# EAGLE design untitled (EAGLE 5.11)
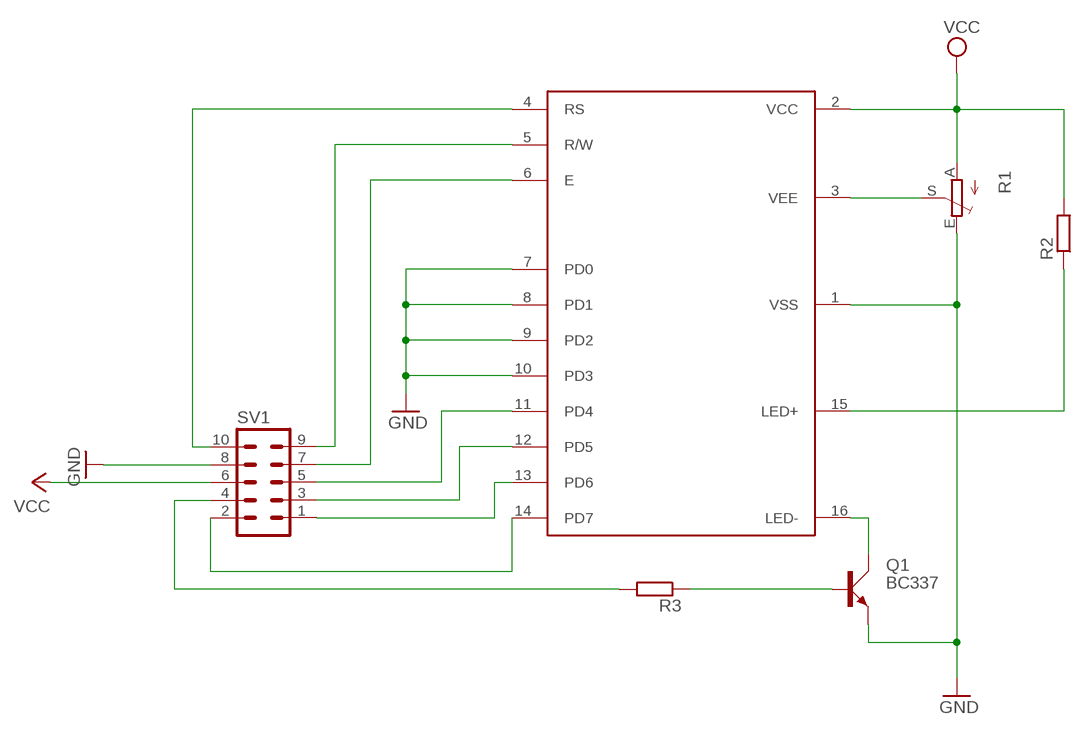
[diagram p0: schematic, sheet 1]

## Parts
Q1  BC337  [SOT54A]
R1  TRIM_EU-LI10  [LI10]
R2  R-EU_0207/10  [0207/10]
R3  R-EU_0207/10  [0207/10]
SV1  ML10L  [ML10L]
U$1  RTR  [TRTRR]

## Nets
GND: Q1.E R1.E SV1.8 U$1.1(VSS) U$1.7(PD0) U$1.8(PD1) U$1.9(PD2) U$1.10(PD3)
N$1: R1.S U$1.3(VEE)
N$3: Q1.C U$1.16(LED-)
N$4: Q1.B R3.1
N$5: R2.1 U$1.15(LED+)
N$6: SV1.2 U$1.14(PD7)
N$7: SV1.1 U$1.13(PD6)
N$8: SV1.3 U$1.12(PD5)
N$9: R3.2 SV1.4
N$10: SV1.7 U$1.6(E)
N$11: SV1.10 U$1.4(RS)
N$12: SV1.5 U$1.11(PD4)
N$14: SV1.9 U$1.5(R/W)
VCC: R1.A R2.2 SV1.6 U$1.2(VCC)

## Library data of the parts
Q1 = transistor-small-signal:BC337: NPN TRANSISTOR
R1 = pot:TRIM_EU-: POTENTIOMETER
R2 R3 = rcl:R-EU_: RESISTOR, European symbol
SV1 = con-ml:ML10L: HARTING; OC_FARNELL: unknown; OC_NEWARK: unknown
U$1 = 4x20lcd:RTR

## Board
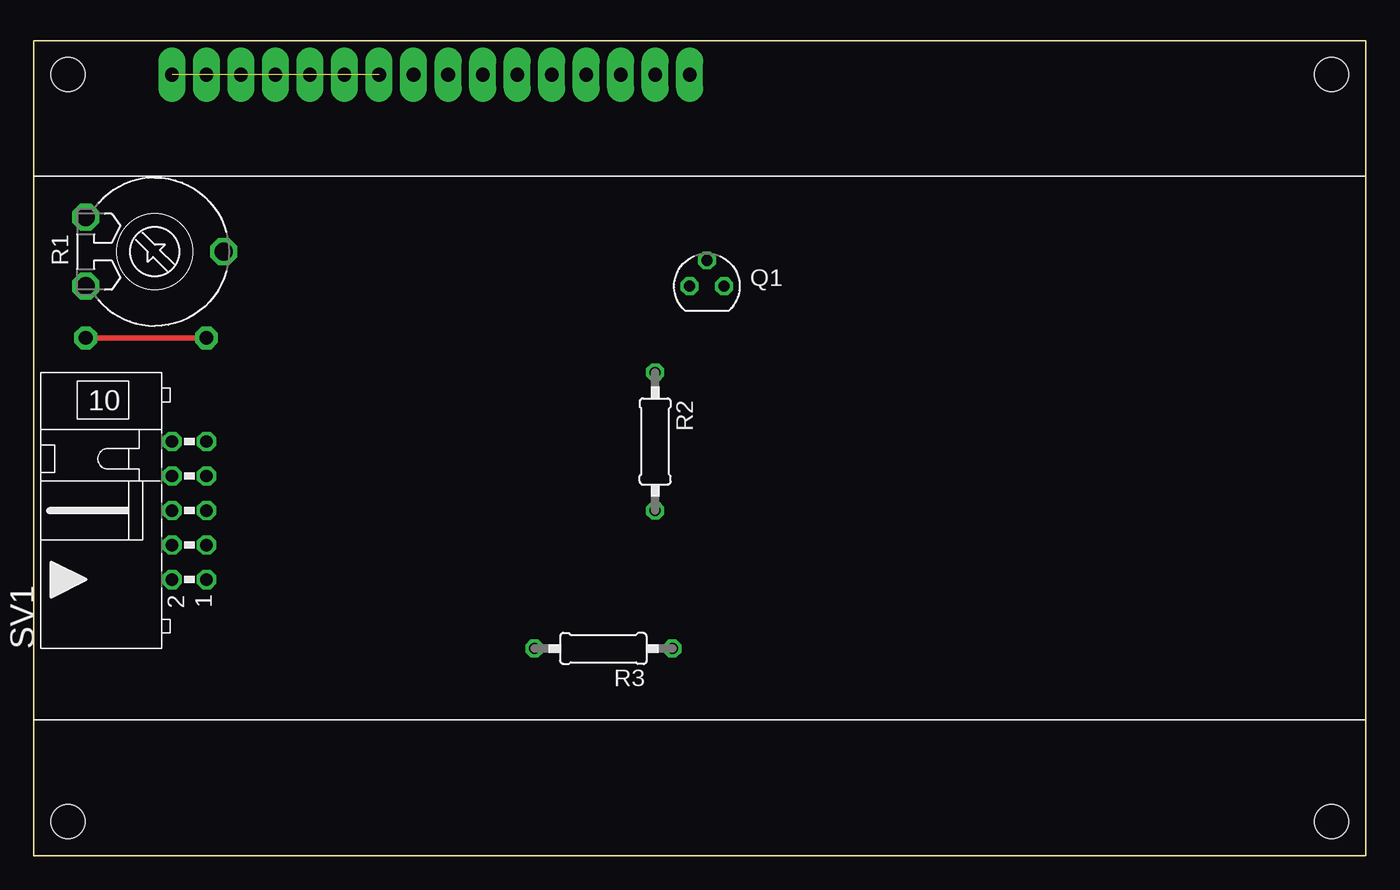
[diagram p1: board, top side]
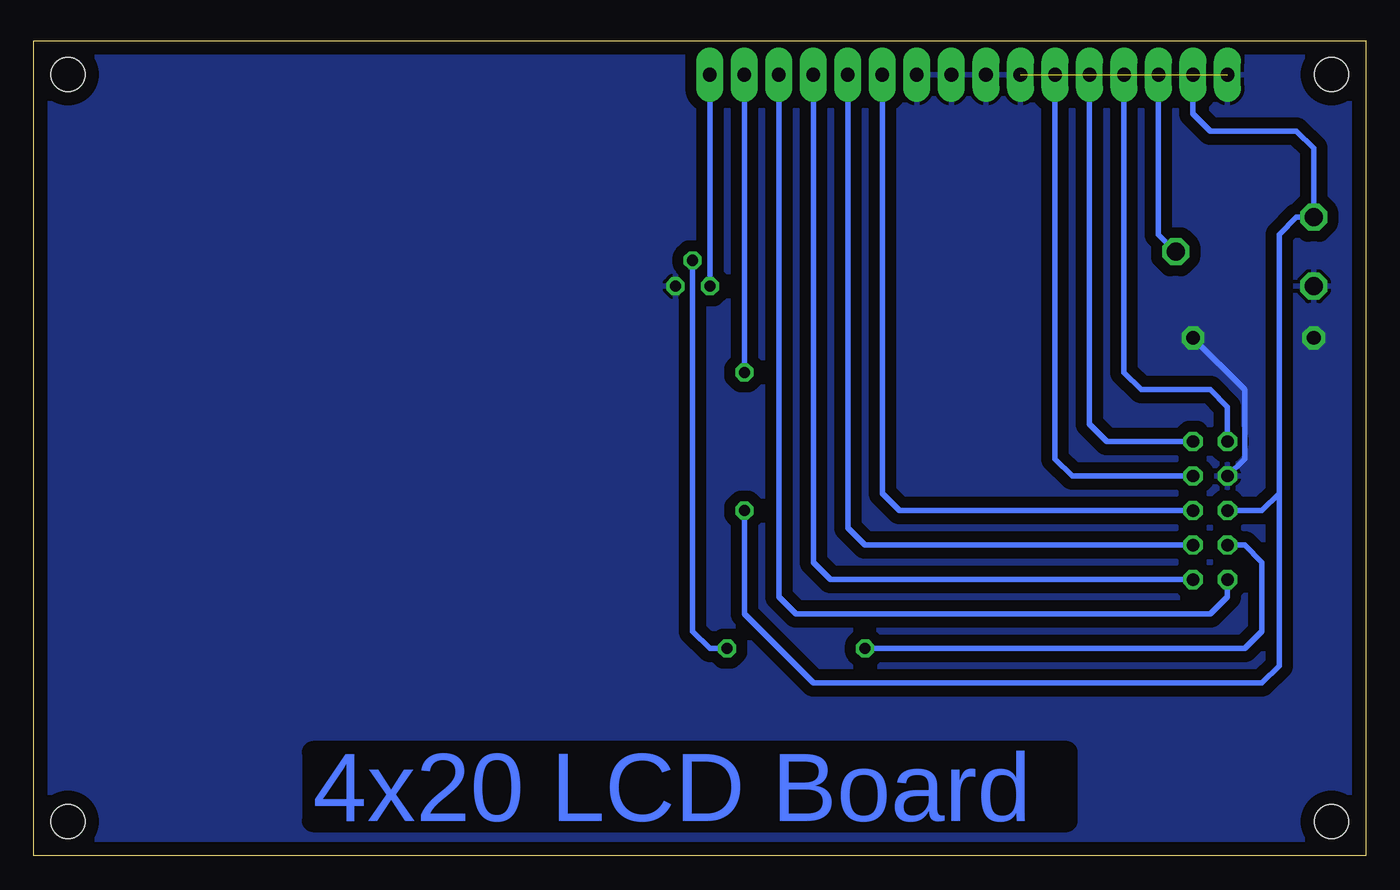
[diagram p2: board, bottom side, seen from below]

Size 98 x 60 mm. Coordinates in mm from the lower left corner, seen from the top.
Outline: 0,0 98,0 98,60 0,60 0,0
Copper layers (1*16): Top 0.035mm / dielectric 1.5mm / Bottom 0.035mm
Design rules "default": minimum track width 10mil, minimum drill 24mil, track to track 8mil, track to pad 8mil, pad to pad 8mil, via to via 8mil, smd to smd 8mil, copper to edge 40mil, drill to drill 8mil, minimum pad ring 10mil, minimum via ring 8mil, stop-mask expansion 4mil, vias tented up to drill 0mil, thermal gap 10mil

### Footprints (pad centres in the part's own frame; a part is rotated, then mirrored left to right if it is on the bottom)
SOT54A = drill 0.813 octagon: B 0,1.905; C -1.27,0; E 1.27,0
LI10 = drill 1.321 octagon: A -2.54,-5.08; E 2.54,-5.08; S 0,5.08
0207/10 = drill 0.813 octagon: 1 -5.08,0; 2 5.08,0
ML10L = drill 0.914 octagon: 1 -5.08,-1.27; 2 -5.08,1.27; 3 -2.54,-1.27; 4 -2.54,1.27; 5 0,-1.27; 6 0,1.27; 7 2.54,-1.27; 8 2.54,1.27; 9 5.08,-1.27; 10 5.08,1.27
TRTRR = drill 1 pad 2 long: 1 10.16,57.48; 2 12.7,57.48; 3 15.24,57.48; 4 17.78,57.48; 5 20.32,57.48; 6 22.86,57.48; 7 25.4,57.48; 8 27.94,57.48; 9 30.48,57.48; 10 33.02,57.48; 11 35.56,57.48; 12 38.1,57.48; 13 40.64,57.48; 14 43.18,57.48; 15 45.72,57.48; 16 48.26,57.48 | hole 2.5: 2.5,57.5; 95.5,57.5; 95.5,2.5; 2.5,2.5

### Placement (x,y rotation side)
DRILEGEND  [DRILEGEND]  not placed on the board
Q1  49.53,41.91 0 top
R1  8.89,44.45 270 top
R2  45.72,30.48 270 top
R3  41.91,15.24 180 top
SV1  11.43,25.4 90 top
U$1  0,0 0 top

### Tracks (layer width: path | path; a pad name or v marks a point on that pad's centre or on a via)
GND  (via drill 1 pad 1.68)  (1 unrouted)
  Top 0.406: v12.7,38.1 v3.81,38.1
  Bottom 0.406: SV1.8 8.89,29.21 8.89,34.29 v12.7,38.1
  pour Bottom (isolate 0.813): 0,59.69 0,0 97.79,0 97.79,59.69
N$1
  Bottom 0.406: U$1.3 15.24,45.72 R1.S
N$3
  Bottom 0.406: Q1.C U$1.16
N$4
  Bottom 0.406: R3.1 48.26,15.24 49.53,16.51 Q1.B
N$5
  Bottom 0.406: R2.1 U$1.15
N$6
  Bottom 0.406: SV1.2 10.16,19.05 11.43,17.78 41.91,17.78 43.18,19.05 U$1.14
N$7
  Bottom 0.406: SV1.1 39.37,20.32 40.64,21.59 U$1.13
N$8
  Bottom 0.406: SV1.3 36.83,22.86 38.1,24.13 U$1.12
N$9
  Bottom 0.406: SV1.4 8.89,22.86 7.62,21.59 7.62,16.51 8.89,15.24 R3.2
N$10
  Bottom 0.406: SV1.7 21.59,27.94 22.86,29.21 U$1.6
N$11
  Bottom 0.406: SV1.10 10.16,33.02 11.43,34.29 16.51,34.29 17.78,35.56 U$1.4
N$12
  Bottom 0.406: SV1.5 34.29,25.4 35.56,26.67 U$1.11
N$14
  Bottom 0.406: SV1.9 19.05,30.48 20.32,31.75 U$1.5
VCC
  Bottom 0.406: R2.2 45.72,17.78 40.64,12.7 7.62,12.7 6.35,13.97 6.35,26.67 | U$1.2 12.7,54.61 11.43,53.34 5.08,53.34 3.81,52.07 R1.A 5.08,46.99 6.35,45.72 6.35,26.67 | SV1.6 7.62,25.4 6.35,26.67

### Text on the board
Bottom: 4x20 LCD Board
